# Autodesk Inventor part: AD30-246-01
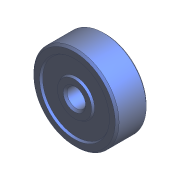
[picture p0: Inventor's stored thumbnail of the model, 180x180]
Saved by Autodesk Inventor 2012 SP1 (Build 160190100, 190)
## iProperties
Created: 2000-07
Part Number: AD30-246-01
Description: DETENT ROLLER
Document SubType Name: Modeling
Designer: Ron
Density: 1 g/cm^3
Material: Default
Author: Ron
Revision Number: A
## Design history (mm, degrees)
derived "detent roller.ipt"
body "Solid1"
tag "TaggingFeature2"
feature "Solid1::detent roller.ipt" dims "ScaleForDerivedMember" = 10
